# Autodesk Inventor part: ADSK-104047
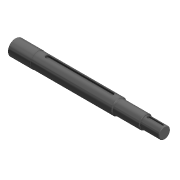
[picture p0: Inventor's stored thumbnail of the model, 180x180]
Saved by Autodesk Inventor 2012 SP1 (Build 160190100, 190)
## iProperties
Shininess: 0.0
Created: 2000-11
Part Number: ADSK-104047
Description: AISI 1040 DIA. 2-1/4" x 20" LONG
Document SubType Name: Modeling
Stock Number: ADSK-104047
Density: 1 g/cm^3
Material: Default
Density: 0.0
Volumn: 0.0
Area: 0.0
PropertySet Name: Model Information
Control State: 0
Master: False
Checked Out: False
Author: gao
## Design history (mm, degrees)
node "Revolution1" dims "d8" = 360 deg
  sketch "Sketch1"
    geometry: L1 (-27.875, 14.644)-(48.325, 14.644); L2 (473.775, 7.504)-(473.775, -11.55); L3 (473.775, -11.55)-(-27.875, -11.55); L4 (-27.875, -11.55)-(-27.875, 14.644); L5 (48.325, 14.644)-(48.325, 13.85); L6 (48.325, 13.85)-(321.375, 13.85); L7 (321.375, 13.85)-(321.375, 10.675); L8 (321.375, 10.675)-(410.275, 10.675); L9 (410.275, 10.675)-(410.275, 7.504); L10 (410.275, 7.504)-(473.775, 7.504)
    constraints: 20 end point, 5 parallel, 4 perpendicular, 1 horizontal
    dimensions: "d0" = 26.19375 distance of L3.end L1.start; "d1" = 501.65 distance of L2.end L3.end; "d2" = 76.2 distance of L1.end L1.start; "d3" = 63.5 distance of L9.end L2.start; "d4" = 88.9 distance of L7.end L8.end; "d5" = 25.4 distance between parallel lines of L3 L6; "d6" = 22.225 distance between parallel lines of L3 L8; "d7" = 19.05365 distance between parallel lines of L3 L10
node "Chamfer1" dims "d9" = 1.5875, "d10" = 1.5875, "d25" = 45 deg
node "Chamfer2" dims "d12" = 1.5875, "d13" = 1.5875, "d26" = 45 deg
node "Fillet2" dims "d14" = 1.5875
workplane "Work Plane1"
workaxis "Work Axis1"
node "Extrusion1" dims "d18" = 4.7625, "d19" = 0
  sketch "Sketch2"
    geometry: L1 (570.23, 0)-(-132.08, 0) reference; L2 (-22.225, 4.762)-(22.225, 4.763); L3 (-22.225, -4.762)-(22.225, -4.763); L4 (-31.75, -17.466)-(-31.75, 17.466) reference; A1 r 4.763 centre (-22.225, 0) between (-22.225, 4.762) and (-22.225, -4.762); A2 r 4.763 centre (22.225, 0) between (22.225, -4.763) and (22.225, 4.763)
    constraints: 4 end point, 4 point on circle, 2 centre point, 2 point on line, 2 tangent, 1 equal radius
    dimensions: "d15" = 9.525 diameter of A1; "d16" = 9.525 distance from line of L4 A1.centre; "d17" = 44.45 distance of A2.centre A1.centre
workplane "Work Plane2"
node "Extrusion2" dims "d23" = 6.35, "d24" = 0
  sketch "Sketch3"
    geometry: L1 (313.055, 0)-(-389.255, 0) reference; L2 (-136.525, -23.812)-(-136.525, 23.812) reference; L3 (-111.125, 6.35)-(104.775, 6.35); L4 (-111.125, -6.35)-(104.775, -6.35); A1 r 6.35 centre (-111.125, 0) between (-111.125, 6.35) and (-111.125, -6.35); A2 r 6.35 centre (104.775, 0) between (104.775, -6.35) and (104.775, 6.35)
    constraints: 4 end point, 4 point on circle, 2 centre point, 2 point on line, 2 tangent, 1 equal radius
    dimensions: "d20" = 25.4 distance from line of L2 A1.centre; "d21" = 12.7 diameter of A1; "d22" = 215.9 distance of A2.centre A1.centre
body "Solid1"
